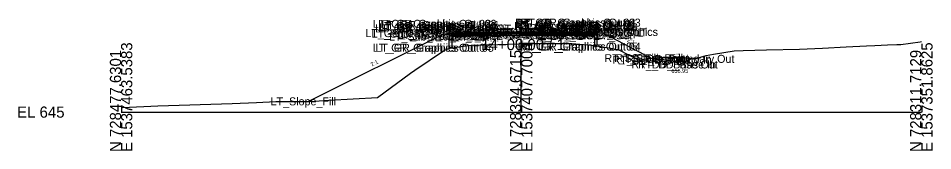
# Model space of a CAD drawing. Extents: x -26 to 1203, y -10 to 9522.
# Drawn here: x -25.7 to 202.8, y 3990.3 to 4023.5 of the extents above; entities that cross this region are included whole.
import ezdxf

# ---------------------------------------------------------------- set-up
doc = ezdxf.new("R2010")
doc.units = 0
for name, color, linetype in [('Default', 7, 'Continuous'), ('Exist Cross Section Cell', 7, 'Continuous'), ('Exist XS Center Line Elevation Label', 7, 'Continuous'), ('Exist XS Ground Line', 7, 'Continuous'), ('Old_Level_63', 7, 'Continuous'), ('Prop CMT Ditch DDE', 7, 'Continuous'), ('Prop CMT Guardrail Graphics', 7, 'Continuous'), ('Prop CMT Pvmt Course 1', 7, 'Continuous'), ('Prop CMT Pvmt Course 2', 7, 'Continuous'), ('Prop CMT Pvmt Course 3', 7, 'Continuous'), ('Prop CMT Pvmt Surface', 7, 'Continuous'), ('Prop CMT Pvmt Surface Overlay', 7, 'Continuous'), ('Prop CMT Pvmt Surface Shoulder', 7, 'Continuous'), ('Prop CMT Shld Paved Course 1', 7, 'Continuous'), ('Prop CMT Shld Paved Course 2', 7, 'Continuous'), ('Prop CMT Shld Paved Course 3', 7, 'Continuous'), ('Prop CMT Slope Grass', 7, 'Continuous'), ('Prop CMT Subgrade Earthwork', 7, 'Continuous'), ('Prop Superelevation  Arrow CELL', 7, 'Continuous'), ('Prop XS Ditch Slope Text', 7, 'Continuous'), ('Prop XS Ditch Standard Text', 7, 'Continuous'), ('Prop XS EOT Tick Mark', 7, 'Continuous'), ('Prop XS SE Text', 7, 'Continuous'), ('Prop XS Side Slope Text', 7, 'Continuous')]:
    doc.layers.add(name, color=color, linetype=linetype)

msp = doc.modelspace()

# ---------------------------------------------------------------- linework, layer by layer
at = {"layer": 'Exist Cross Section Cell'}
for p, q in [((100, 4000), (100, 4018.34)), ((0, 4000), (100, 4000)), ((100, 4000), (200, 4000))]:
    msp.add_line(p, q, dxfattribs=at)
at = {"layer": 'Exist XS Ground Line'}
msp.add_lwpolyline([(0, 4001.11), (0.39, 4001.12), (9.17, 4001.55), (27.8, 4002.18), (33.83, 4002.45), (38.68, 4002.69), (43.15, 4002.69), (45.34, 4002.67), (47.05, 4002.7), (51.93, 4003.03), (64.06, 4003.69), (72.32, 4009.8), (73.37, 4010.56), (80.79, 4015.57), (82.25, 4016.01), (84.97, 4016.47), (87.45, 4016.78), (94.18, 4016.98), (99.57, 4017.16), (100, 4017.17), (105.39, 4017.19), (112.65, 4017.21), (118.54, 4016.69), (123.75, 4015.78), (124.19, 4015.73), (124.37, 4015.64), (129.22, 4013.12), (132.39, 4013.44), (135.5, 4013.82), (139.98, 4013.81), (143.35, 4013.36), (146.25, 4014.19), (148.08, 4014.56), (153.2, 4015.34), (155.5, 4015.47), (161.34, 4015.64), (169.55, 4015.77), (175.32, 4016.02), (181.25, 4016.4), (186.3, 4016.65), (188.35, 4016.74), (191.55, 4016.84), (193.91, 4016.92), (194.39, 4016.93), (194.87, 4016.99), (199.72, 4017.65), (200, 4017.69)], dxfattribs=at)
at = {"layer": 'Prop CMT Ditch DDE'}
for points in [[(132.65, 4013.47), (137.65, 4013.07), (139.6, 4011.95)], [(139.6, 4011.95), (142.62, 4013.46)]]:
    msp.add_lwpolyline(points, dxfattribs=at)
at = {"layer": 'Prop CMT Guardrail Graphics'}
for points in [[(118.98, 4022.44), (117.64, 4022.44), (117.37, 4022.15)], [(118.98, 4016.44), (118.98, 4022.44)], [(81.99, 4016.14), (81.99, 4022.14)], [(81.99, 4022.14), (83.32, 4022.14), (83.6, 4021.85)], [(83.6, 4021.27), (83.32, 4020.98), (82.66, 4020.98)], [(82.66, 4020.98), (82.66, 4016.14)], [(83.6, 4021.85), (83.32, 4021.56)], [(83.32, 4021.56), (83.6, 4021.27)], [(117.37, 4022.15), (117.64, 4021.86)], [(117.64, 4021.86), (117.37, 4021.57)], [(117.37, 4021.57), (117.64, 4021.27), (118.31, 4021.27)], [(118.31, 4021.27), (118.31, 4016.44)], [(82.66, 4016.14), (81.99, 4016.14)], [(118.31, 4016.44), (118.98, 4016.44)]]:
    msp.add_lwpolyline(points, dxfattribs=at)
at = {"layer": 'Prop CMT Pvmt Course 1'}
for points in [[(100, 4020.14), (89, 4019.92)], [(89, 4019.92), (89, 4019.67)], [(89, 4019.67), (100, 4019.89)], [(100, 4019.89), (100, 4020.14)], [(100, 4020.14), (111, 4020.12)], [(100, 4019.89), (100, 4020.14)], [(100, 4019.89), (100, 4019.89), (100, 4019.89)], [(111, 4019.87), (100, 4019.89)], [(100, 4019.89), (100, 4019.89), (100, 4019.89)], [(111, 4020.12), (111, 4019.87)]]:
    msp.add_lwpolyline(points, dxfattribs=at)
at = {"layer": 'Prop CMT Pvmt Course 2'}
for points in [[(100, 4019.89), (89, 4019.67)], [(100, 4019.68), (100, 4019.89)], [(100, 4019.68), (100, 4019.89)], [(100, 4019.89), (111, 4019.87)], [(89, 4019.46), (100, 4019.68)], [(89, 4019.67), (89, 4019.46)], [(111, 4019.66), (100, 4019.68)], [(111, 4019.87), (111, 4019.66)]]:
    msp.add_lwpolyline(points, dxfattribs=at)
at = {"layer": 'Prop CMT Pvmt Course 3'}
for points in [[(100, 4019.68), (89, 4019.46)], [(89, 4019.46), (89, 4019.09)], [(89, 4019.09), (100, 4019.31)], [(100, 4019.31), (100, 4019.68)], [(100, 4019.68), (111, 4019.66)], [(100, 4019.31), (100, 4019.68)], [(111, 4019.29), (100, 4019.31)], [(111, 4019.66), (111, 4019.29)]]:
    msp.add_lwpolyline(points, dxfattribs=at)
at = {"layer": 'Prop CMT Pvmt Surface'}
for points in [[(100, 4020.14), (89, 4019.92)], [(100, 4020.14), (111, 4020.12)]]:
    msp.add_lwpolyline(points, dxfattribs=at)
at = {"layer": 'Prop CMT Pvmt Surface Overlay'}
for points in [[(100, 4020.14), (89, 4019.92)], [(100, 4020.14), (111, 4020.12)]]:
    msp.add_lwpolyline(points, dxfattribs=at)
at = {"layer": 'Prop CMT Pvmt Surface Shoulder'}
for points in [[(89, 4019.92), (83.61, 4019.81)], [(111, 4020.12), (117.37, 4020.11)]]:
    msp.add_lwpolyline(points, dxfattribs=at)
at = {"layer": 'Prop CMT Shld Paved Course 1'}
for points in [[(89, 4019.92), (83.61, 4019.81), (83.35, 4019.56)], [(89, 4019.67), (89, 4019.92)], [(111, 4020.12), (117.37, 4020.11), (117.62, 4019.86)], [(111, 4019.87), (111, 4020.12)], [(83.35, 4019.56), (89, 4019.67)], [(117.62, 4019.86), (111, 4019.87)]]:
    msp.add_lwpolyline(points, dxfattribs=at)
at = {"layer": 'Prop CMT Shld Paved Course 2'}
for points in [[(89, 4019.67), (83.35, 4019.56), (83.14, 4019.34)], [(83.14, 4019.34), (89, 4019.46)], [(89, 4019.46), (89, 4019.67)], [(111, 4019.87), (117.62, 4019.86), (117.82, 4019.65)], [(111, 4019.66), (111, 4019.87)], [(117.82, 4019.65), (111, 4019.66)]]:
    msp.add_lwpolyline(points, dxfattribs=at)
at = {"layer": 'Prop CMT Shld Paved Course 3'}
for points in [[(83.14, 4019.34), (82.76, 4018.96)], [(82.76, 4018.96), (89, 4019.09)], [(89, 4019.46), (83.14, 4019.34)], [(83.14, 4019.34), (83.14, 4019.34)], [(89, 4019.09), (89, 4019.46)], [(111, 4019.66), (117.82, 4019.65)], [(111, 4019.29), (111, 4019.66)], [(118.2, 4019.27), (111, 4019.29)], [(117.82, 4019.65), (117.82, 4019.65)], [(117.82, 4019.65), (118.2, 4019.27)]]:
    msp.add_lwpolyline(points, dxfattribs=at)
at = {"layer": 'Prop CMT Slope Grass'}
for points in [[(117.37, 4020.11), (117.37, 4020.11)], [(117.37, 4020.11), (120.37, 4019.92)], [(120.37, 4019.92), (132.65, 4013.47)], [(80.6, 4019.57), (46.85, 4002.7)], [(83.6, 4019.81), (80.6, 4019.57)], [(83.61, 4019.81), (83.6, 4019.81)]]:
    msp.add_lwpolyline(points, dxfattribs=at)
at = {"layer": 'Prop CMT Subgrade Earthwork'}
for points in [[(118.2, 4019.27), (118.94, 4020.01)], [(82.76, 4018.96), (82.03, 4019.69)], [(89, 4019.09), (82.76, 4018.96)], [(100, 4019.31), (89, 4019.09)], [(100, 4019.31), (111, 4019.29)], [(111, 4019.29), (118.2, 4019.27)]]:
    msp.add_lwpolyline(points, dxfattribs=at)
at = {"layer": 'Prop Superelevation  Arrow CELL'}
for p, q in [((97.13, 4020.68), (91.13, 4020.56)), ((103.21, 4020.71), (109.21, 4020.59))]:
    msp.add_line(p, q, dxfattribs=at)
for points in [[(91.13, 4020.56), (92.62, 4021.09), (92.28, 4020.59)], [(109.21, 4020.59), (107.72, 4021.12), (108.05, 4020.61)]]:
    msp.add_lwpolyline(points, close=True, dxfattribs=at)
at = {"layer": 'Prop XS EOT Tick Mark'}
for points in [[(89, 4019.92), (89, 4020.92)], [(111, 4020.12), (111, 4021.12)]]:
    msp.add_lwpolyline(points, dxfattribs=at)

# ---------------------------------------------------------------- texts
at = {"layer": 'Default'}
msp.add_text('-', height=0.0001, dxfattribs=at).set_placement((0, 4000))
msp.add_text('-', height=0.0001, dxfattribs=at).set_placement((0, 4000))
msp.add_text('-', height=0.0001, dxfattribs=at).set_placement((0, 4000))
at = {"layer": 'Exist Cross Section Cell'}
for s, p in [('L', (90, 4018.34)), ('14+00.00 / 1', (90, 4015.54)), ('EL 645', (-26, 3998.6))]:
    msp.add_text(s, height=2.8, dxfattribs=at).set_placement(p)
for s, p in [('N 728477.6301', (0, 3990)), ('E 1537463.5383', (2.8, 3990)), ('N 728394.6715', (100, 3990)), ('E 1537407.7004', (102.8, 3990)), ('N 728311.7129', (200, 3990)), ('E 1537351.8625', (202.8, 3990))]:
    msp.add_text(s, height=2.8, rotation=90, dxfattribs=at).set_placement(p)
at = {"layer": 'Exist XS Center Line Elevation Label'}
msp.add_text('662.17', height=0.75, dxfattribs=at).set_placement((98.5, 4016.03))
at = {"layer": 'Old_Level_63'}
for s, p in [('LT_GR_Graphics Out 03', (62.89, 4021.14)), ('LT_GR_Graphics Out 02', (64.22, 4021.14)), ('LT_GR_Graphics Out 09', (64.22, 4020.56)), ('LT_GR_Graphics Out 08', (64.49, 4020.27)), ('LT_GR_Graphics Out 01', (65.06, 4020.85)), ('RT_GR_Graphics Out 08', (98.22, 4020.57)), ('RT_GR_Graphics Out 02', (98.49, 4021.44)), ('RT_GR_Graphics Out 09', (98.49, 4020.86)), ('RT_GR_Graphics Out 07', (98.49, 4020.27)), ('RT_GR_Graphics Out 01', (98.79, 4021.15)), ('RT_GR_Graphics Out 06', (99.11, 4020.27)), ('RT_GR_Graphics Out 03', (99.83, 4021.44)), ('LT_GS_OS_GR_Face_Graphics', (61.05, 4018.81)), ('LT_Sub_Trench_Out_DLT', (62.6, 4018.69)), ('LT_GR_Graphics Out 06', (63.51, 4019.98)), ('LT_GR_Graphics Out 07', (64.22, 4019.98)), ('LT_Sub_Trench_Out', (66.96, 4017.96)), ('LT_PS3_Shelf_Out', (69.12, 4018.34)), ('LT_GS_OS_CTL', (69.97, 4018.57)), ('LT_PS3_OEOP', (73.37, 4018.34)), ('LT_PS2_OEOP', (73.59, 4018.56)), ('LT_PS1_OEOP', (74.41, 4018.81)), ('LT_Sub_OEOT', (79.08, 4018.09)), ('LT_PV2_OEOT', (79.17, 4018.67)), ('LT_PV3_OEOT', (79.17, 4018.46)), ('LT_PV1_OEOT', (79.74, 4018.92)), ('LT_TM_OEOT', (79.94, 4019.92)), ('RT_PV1_OEEOP_W', (87.94, 4018.89)), ('LT_PV1_OEEOP_W', (87.98, 4018.89)), ('RT_Sub_OEEOP', (89.17, 4018.31)), ('LT_Sub_OEEOP', (89.21, 4018.31)), ('RT_PV2_OEEOP', (89.26, 4018.89)), ('RT_PV3_OEEOP', (89.26, 4018.68)), ('LT_PV2_OEEOP', (89.31, 4018.89)), ('LT_PV3_OEEOP', (89.31, 4018.68)), ('RT_Seek SS Fill O', (89.44, 4019.14)), ('PV1_PGL_W', (92.58, 4018.89)), ('PV1_PGL', (94.47, 4019.14)), ('RT_GS_OS_GR_Face_Graphics', (94.78, 4019.11)), ('RT_Sub_Trench_Out_DLT', (99.46, 4019.01)), ('RT_Sub_OEOT', (101.03, 4018.29)), ('RT_PV2_OEOT', (101.13, 4018.87)), ('RT_PV3_OEOT', (101.13, 4018.66)), ('RT_PV1_OEOT', (101.69, 4019.12)), ('RT_TM_OEOT', (101.9, 4020.12)), ('RT_Sub_Trench_Out', (102.36, 4018.27)), ('RT_PS3_Shelf_Out', (103.76, 4018.65)), ('RT_PS2_OEOP', (107.81, 4018.86)), ('RT_PS3_OEOP', (108.01, 4018.65)), ('RT_PS1_OEOP', (108.12, 4019.11)), ('RT_GS_OS_CTL', (109.7, 4018.92)), ('LT_GR_Graphics Out 04', (62.89, 4015.14)), ('LT_GR_Graphics Out 05', (63.56, 4015.14)), ('RT_GR_Graphics Out 05', (99.16, 4015.44)), ('RT_GR_Graphics Out 04', (99.83, 4015.44)), ('RT_SS_Fill_Point', (120.79, 4012.53)), ('RT_DD_Boundary In', (122.8, 4012.13)), ('RT_Slope_Fill', (123.62, 4012.53)), ('RT_DD_Boundary Out', (126.37, 4012.36)), ('RT_DD_Base Out', (127.56, 4010.95)), ('RT_DD_Base In', (129.18, 4010.95)), ('LT_Slope_Fill', (37.37, 4001.7))]:
    msp.add_text(s, height=2, dxfattribs=at).set_placement(p)
at = {"layer": 'Prop XS Ditch Slope Text'}
for rotation, p in [(26.5651, (141.71, 4011.48)), (333.4349, (136.76, 4012.01))]:
    msp.add_text('2:1', height=1, rotation=rotation, dxfattribs=at).set_placement(p)
at = {"layer": 'Prop XS Ditch Standard Text'}
msp.add_text('656.95', height=1, dxfattribs=at).set_placement((137.53, 4009.84))
at = {"layer": 'Prop XS SE Text'}
for s, rotation, p in [('0.020', 1.1458, (92.73, 4020.99)), ('0.002', 359.8955, (103.79, 4021.13))]:
    msp.add_text(s, height=1, rotation=rotation, dxfattribs=at).set_placement(p)
at = {"layer": 'Prop XS Side Slope Text'}
for rotation, p in [(333.4349, (126.39, 4017.75)), (26.5651, (62.68, 4011.45))]:
    msp.add_text('2:1', height=1, rotation=rotation, dxfattribs=at).set_placement(p)

doc.saveas('drawing.dxf')
